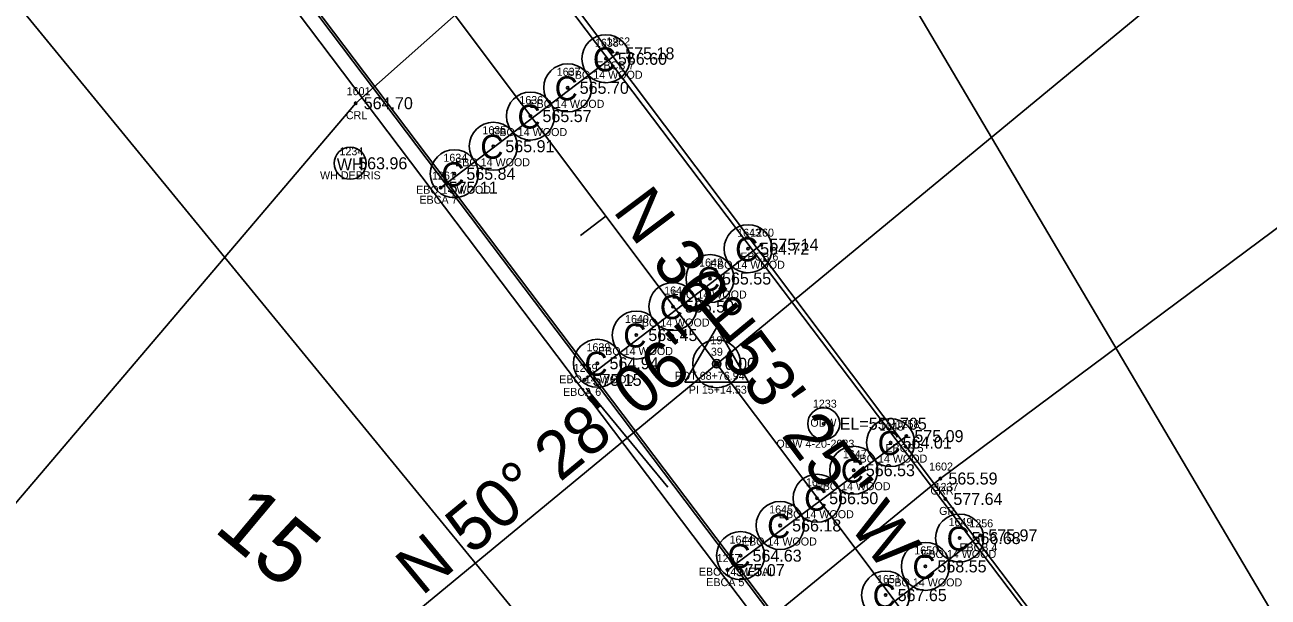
# Model space of a CAD drawing. Extents: x 1694813 to 1696862, y 1086485 to 1091027.
# Drawn here: x 1695795.8 to 1695951.1, y 1089028.7 to 1089100.2 of the extents above; entities that cross this region are included whole.
import ezdxf

# ---------------------------------------------------------------- set-up
doc = ezdxf.new("R2010")
doc.units = 0
for name, color, linetype in [('RD_EX_Bridge', 7, 'Continuous'), ('RD_EX_Bridge_txCode', 7, 'Continuous'), ('RD_EX_GuardRail', 7, 'Continuous'), ('RD_EX_GuardRail_txCode', 7, 'Continuous'), ('RD_EX_H2O', 7, 'Continuous'), ('RD_EX_H2O_txCode', 7, 'Continuous'), ('RD_EX_Misc', 7, 'Continuous'), ('RD_EX_TX_Bridge_ELEV', 7, 'Continuous'), ('RD_EX_TX_GuardRail_ELEV', 7, 'Continuous'), ('RD_EX_TX_H2O_ELEV', 7, 'Continuous'), ('RD_EX_VEG', 7, 'Continuous'), ('RD_HC_Cl', 7, 'Continuous'), ('RD_HC_Data', 7, 'Continuous'), ('RD_HC_Data_Tic', 7, 'Continuous'), ('RD_HC_Survey_ELEV', 7, 'Continuous'), ('RD_HC_TX_Sta50', 7, 'Continuous'), ('RD_HC_txCode', 7, 'Continuous'), ('RD_SMD_Locator', 7, 'Continuous')]:
    doc.layers.add(name, color=color, linetype=linetype)

msp = doc.modelspace()

# ---------------------------------------------------------------- linework, layer by layer
at = {"layer": 'RD_EX_Bridge'}
for p, q in [((1695847.7, 1089079.83), (1695869.76, 1089096.61)), ((1695865.67, 1089055.82), (1695887.77, 1089072.72)), ((1695883.54, 1089032.04), (1695905.88, 1089048.79)), ((1695893.25, 1089019.58), (1695915.11, 1089036.39))]:
    msp.add_line(p, q, dxfattribs=at)
msp.add_lwpolyline([(1695941.01, 1089000.23), (1695920.78, 1088984.87), (1695803.35, 1089140.32), (1695823.67, 1089155.36), (1695941.01, 1089000.23)], dxfattribs=at)
for centre in [(1695868.34, 1089095.94), (1695863.57, 1089092.31), (1695858.92, 1089088.78), (1695854.28, 1089085.01), (1695849.41, 1089081.57), (1695886.11, 1089072.2), (1695881.35, 1089068.48), (1695876.71, 1089064.98), (1695872.14, 1089061.42), (1695867.29, 1089057.89), (1695903.91, 1089047.98), (1695899.31, 1089044.53), (1695894.73, 1089041.03), (1695890.11, 1089037.62), (1695912.52, 1089036.05), (1695885.16, 1089033.85), (1695908.26, 1089032.51), (1695903.29, 1089028.92)]:
    msp.add_circle(centre, 3, dxfattribs=at)
at = {"layer": 'RD_EX_GuardRail'}
for points in [[(1695954.25, 1088939.4), (1695922.07, 1088982.8), (1695888.95, 1089026.55), (1695824.62, 1089111.72), (1695774.33, 1089183.16), (1695747.02, 1089230.32), (1695728.79, 1089274.77), (1695712.04, 1089332.59)], [(1695975.12, 1088955.36), (1695942.2, 1088999.47), (1695910.75, 1089040.94), (1695844.49, 1089129.18), (1695795.31, 1089197.37)]]:
    msp.add_lwpolyline(points, dxfattribs=at)
at = {"layer": 'RD_EX_H2O'}
for points in [[(1695741.44, 1088979.77), (1695766.31, 1089008.66), (1695772.21, 1089014.13), (1695837.09, 1089090.39), (1695860.76, 1089111.44), (1695929.31, 1089152.28), (1696035.3, 1089183.03), (1696164.17, 1089149.21), (1696221.7, 1089111.38), (1696248.95, 1089080.06), (1696273.19, 1089047.83), (1696283.59, 1089011.28), (1696295.68, 1088944.39)], [(1695520.92, 1088704.05), (1695627.53, 1088770.84), (1695697.51, 1088817.15), (1695757.08, 1088884.85), (1695828.4, 1088961.5), (1695887.69, 1089025.09), (1695910.13, 1089043.49), (1695963.83, 1089083.42), (1696041.69, 1089105.91), (1696137.07, 1089082.48), (1696174.24, 1089034.61), (1696185.76, 1089011.54), (1696200.45, 1088973.14), (1696214.06, 1088899.28)]]:
    msp.add_lwpolyline(points, dxfattribs=at)
for centre, radius in [((1695836.4, 1089082.88), 2), ((1695836.4, 1089082.88), 0.005), ((1695895.55, 1089050.34), 2), ((1695895.55, 1089050.34), 0.15)]:
    msp.add_circle(centre, radius, dxfattribs=at)
at = {"layer": 'RD_EX_Misc'}
msp.add_line((1695918.59, 1088984.27), (1695801.38, 1089139.4), dxfattribs=at)
at = {"layer": 'RD_EX_VEG'}
for points in [[(1695767.04, 1087738.17), (1695850.84, 1087719.29), (1695876.92, 1087874.52), (1695886.77, 1087978.73), (1695882.04, 1088123.19), (1695966.35, 1088397.22), (1695987.61, 1088500.99), (1696016.82, 1088604.01), (1696023.94, 1088658.84), (1696026.75, 1088706.17), (1696020.44, 1088756.26), (1696012.04, 1088803.02), (1695995.69, 1088847.32), (1695967.16, 1088892.48), (1695790.95, 1089107.47), (1695767.01, 1089177.35), (1695741.24, 1089223.37), (1695720.39, 1089271.33), (1695703.52, 1089329.03), (1695695, 1089381.13)], [(1695933.86, 1087837.25), (1695947.67, 1087971.41), (1695951.18, 1088015.29), (1695955.07, 1088071.66), (1695974.95, 1088229.99), (1695984.06, 1088281.51), (1695991.57, 1088334), (1696002.15, 1088386.49), (1696032.05, 1088491.59), (1696059.12, 1088595.39), (1696074.06, 1088653.09), (1696077.62, 1088703.57), (1696070.4, 1088760.42), (1696059.88, 1088817.29), (1696044.37, 1088867.3), (1696013.5, 1088916.36), (1695990.24, 1088961.27), (1695859.14, 1089183.28), (1695912, 1089200.8)]]:
    msp.add_lwpolyline(points, dxfattribs=at)
at = {"layer": 'RD_HC_Cl'}
for p, q in [((1695971.3, 1088939.1), (1695801.51, 1089165.33)), ((1695799.79, 1088989.83), (1695937.83, 1089103.75))]:
    msp.add_line(p, q, dxfattribs=at)
at = {"layer": 'RD_HC_Data'}
for p, q in [((1695878.22, 1089055.54), (1695882.19, 1089062.42)), ((1695882.19, 1089062.42), (1695886.16, 1089055.54)), ((1695878.22, 1089055.54), (1695886.16, 1089055.54))]:
    msp.add_line(p, q, dxfattribs=at)
for radius in [3, 0.529, 0.282]:
    msp.add_circle((1695882.19, 1089057.83), radius, dxfattribs=at)
at = {"layer": 'RD_HC_Data_Tic'}
for p, q in [((1695868.35, 1089076.27), (1695865.15, 1089073.87)), ((1695870.99, 1089048.59), (1695865.89, 1089054.76)), ((1695870.99, 1089048.59), (1695876.08, 1089042.42))]:
    msp.add_line(p, q, dxfattribs=at)
at = {"layer": 'RD_SMD_Locator'}
for centre in [(1695869.76, 1089096.61), (1695868.34, 1089095.94), (1695863.57, 1089092.31), (1695837.09, 1089090.39), (1695858.92, 1089088.78), (1695854.28, 1089085.01), (1695849.41, 1089081.57), (1695847.7, 1089079.83), (1695886.11, 1089072.2), (1695887.77, 1089072.72), (1695881.35, 1089068.48), (1695876.71, 1089064.98), (1695872.14, 1089061.42), (1695867.29, 1089057.89), (1695882.19, 1089057.83), (1695882.19, 1089057.83), (1695865.67, 1089055.82), (1695905.88, 1089048.79), (1695903.91, 1089047.98), (1695899.31, 1089044.53), (1695910.13, 1089043.49), (1695894.73, 1089041.03), (1695910.75, 1089040.94), (1695890.11, 1089037.62), (1695912.52, 1089036.05), (1695915.11, 1089036.39), (1695885.16, 1089033.85), (1695908.26, 1089032.51), (1695883.54, 1089032.04), (1695903.29, 1089028.92)]:
    msp.add_circle(centre, 0.15, dxfattribs=at)

# ---------------------------------------------------------------- texts
at = {"layer": 'RD_EX_Bridge'}
for p in [(1695866.71, 1089094.37), (1695861.94, 1089090.75), (1695857.29, 1089087.22), (1695852.65, 1089083.45), (1695847.78, 1089080), (1695884.48, 1089070.63), (1695879.72, 1089066.92), (1695875.07, 1089063.41), (1695870.51, 1089059.86), (1695865.66, 1089056.33), (1695902.28, 1089046.42), (1695897.68, 1089042.97), (1695893.1, 1089039.47), (1695888.48, 1089036.06), (1695910.89, 1089034.49), (1695883.53, 1089032.29), (1695906.63, 1089030.95), (1695901.66, 1089027.36)]:
    msp.add_text('C', height=3, dxfattribs=at).set_placement(p)
at = {"layer": 'RD_EX_Bridge_txCode'}
for s, p in [('1638', (1695866.97, 1089097.44)), ('1262', (1695868.39, 1089097.61)), ('1637', (1695862.2, 1089093.81)), ('EBCB 7', (1695867.14, 1089094.61)), ('EBO 14 WOOD', (1695863.56, 1089093.44)), ('1636', (1695857.53, 1089090.28)), ('EBO 14 WOOD', (1695858.79, 1089089.81)), ('1635', (1695852.91, 1089086.51)), ('EBO 14 WOOD', (1695854.14, 1089086.28)), ('1634', (1695848.04, 1089083.07)), ('EBO 14 WOOD', (1695849.5, 1089082.51)), ('1261', (1695846.61, 1089080.83)), ('EBO 14 WOOD', (1695844.63, 1089079.07)), ('EBCA 7', (1695845.05, 1089077.83)), ('1643', (1695884.74, 1089073.7)), ('1260', (1695886.36, 1089073.72)), ('EBCB 6', (1695885.13, 1089070.72)), ('1642', (1695879.98, 1089069.98)), ('EBO 14 WOOD', (1695881.33, 1089069.7)), ('1641', (1695875.62, 1089066.48)), ('EBO 14 WOOD', (1695876.57, 1089065.98)), ('1640', (1695870.73, 1089062.92)), ('EBO 14 WOOD', (1695871.93, 1089062.48)), ('1639', (1695865.92, 1089059.39)), ('EBO 14 WOOD', (1695867.36, 1089058.92)), ('1259', (1695864.32, 1089056.82)), ('EBO 14 WOOD', (1695862.51, 1089055.39)), ('EBCA 6', (1695862.99, 1089053.82)), ('1648', (1695902.54, 1089049.48)), ('1258', (1695904.53, 1089049.79)), ('1647', (1695897.94, 1089046.03)), ('EBCB 5', (1695903.26, 1089046.79)), ('EBO 14 WOOD', (1695899.13, 1089045.48)), ('1646', (1695893.33, 1089042.53)), ('EBO 14 WOOD', (1695894.53, 1089042.03)), ('1645', (1695888.74, 1089039.12)), ('EBO 14 WOOD', (1695889.95, 1089038.53)), ('1649', (1695911.15, 1089037.55)), ('1256', (1695913.74, 1089037.39)), ('1644', (1695883.79, 1089035.35)), ('EBO 14 WOOD', (1695885.33, 1089035.12)), ('1650', (1695906.86, 1089034.01)), ('EBO 14 WOOD', (1695907.74, 1089033.55)), ('EBCB 4', (1695912.49, 1089034.39)), ('1257', (1695882.19, 1089033.04)), ('EBO 14 METAL', (1695879.95, 1089031.35)), ('1651', (1695902.21, 1089030.42)), ('EBCA 5', (1695880.88, 1089030.04)), ('EBO 14 WOOD', (1695903.49, 1089030.01))]:
    msp.add_text(s, height=1, dxfattribs=at).set_placement(p)
at = {"layer": 'RD_EX_GuardRail_txCode'}
for s, p in [('1237', (1695909.4, 1089041.94)), ('GR', (1695909.97, 1089038.94))]:
    msp.add_text(s, height=1, dxfattribs=at).set_placement(p)
at = {"layer": 'RD_EX_H2O'}
for s, height, p in [('WH', 1.5, (1695834.73, 1089082)), ('ODW', 1, (1695893.88, 1089049.96))]:
    msp.add_text(s, height=height, dxfattribs=at).set_placement(p)
at = {"layer": 'RD_EX_H2O_txCode'}
for s, p in [('1601', (1695835.96, 1089091.39)), ('CRL', (1695835.86, 1089088.39)), ('1234', (1695835.06, 1089083.88)), ('WH DEBRIS', (1695832.63, 1089080.88)), ('1233', (1695894.2, 1089052.34)), ('ODW 4-20-2023', (1695889.64, 1089047.34)), ('1602', (1695908.72, 1089044.49)), ('CRR', (1695908.88, 1089041.49))]:
    msp.add_text(s, height=1, dxfattribs=at).set_placement(p)
at = {"layer": 'RD_EX_TX_Bridge_ELEV'}
for s, p in [('566.60', (1695869.84, 1089095.19)), ('575.18', (1695870.76, 1089095.86)), ('565.70', (1695865.07, 1089091.56)), ('565.57', (1695860.42, 1089088.03)), ('565.91', (1695855.78, 1089084.26)), ('565.84', (1695850.91, 1089080.82)), ('575.11', (1695848.7, 1089079.08)), ('575.14', (1695888.77, 1089071.97)), ('564.72', (1695887.61, 1089071.45)), ('565.55', (1695882.85, 1089067.73)), ('565.50', (1695878.21, 1089064.23)), ('565.45', (1695873.64, 1089060.67)), ('564.94', (1695868.79, 1089057.14)), ('575.15', (1695866.67, 1089055.07)), ('564.01', (1695905.41, 1089047.23)), ('575.09', (1695906.88, 1089048.04)), ('566.53', (1695900.81, 1089043.78)), ('566.50', (1695896.23, 1089040.28)), ('566.18', (1695891.61, 1089036.87)), ('566.68', (1695914.02, 1089035.3)), ('575.97', (1695916.11, 1089035.64)), ('564.63', (1695886.66, 1089033.1)), ('575.07', (1695884.54, 1089031.29)), ('568.55', (1695909.76, 1089031.76)), ('567.65', (1695904.79, 1089028.17))]:
    msp.add_text(s, height=1.5, dxfattribs=at).set_placement(p)
at = {"layer": 'RD_EX_TX_GuardRail_ELEV'}
msp.add_text('577.64', height=1.5, dxfattribs=at).set_placement((1695911.75, 1089040.19))
at = {"layer": 'RD_EX_TX_H2O_ELEV'}
for s, p in [('564.70', (1695838.09, 1089089.64)), ('563.96', (1695837.4, 1089082.13)), ('EL=559.705', (1695897.55, 1089049.59)), ('565.59', (1695911.13, 1089042.74))]:
    msp.add_text(s, height=1.5, dxfattribs=at).set_placement(p)
at = {"layer": 'RD_HC_Data'}
for s, rotation, p in [('N 36%%d 53\' 25" W', 306.8901, (1695869.1, 1089076.94)), ('N 50%%d 28\' 06" E', 39.5316, (1695845.34, 1089028.72))]:
    msp.add_text(s, height=6, rotation=rotation, dxfattribs=at).set_placement(p)
at = {"layer": 'RD_HC_Survey_ELEV'}
msp.add_text('0.00', height=1.5, dxfattribs=at).set_placement((1695883.19, 1089057.08))
msp.add_text('0.00', height=1.5, dxfattribs=at).set_placement((1695883.19, 1089057.08))
at = {"layer": 'RD_HC_TX_Sta50'}
msp.add_text('15', height=8, rotation=320.0994, dxfattribs=at).set_placement((1695819.19, 1089037.04))
at = {"layer": 'RD_HC_txCode'}
for s, p in [('19', (1695881.41, 1089060.26)), ('39', (1695881.46, 1089058.83)), ('POT 68+76.94', (1695876.94, 1089055.83)), ('PI 15+14.53', (1695878.69, 1089054.09))]:
    msp.add_text(s, height=1, dxfattribs=at).set_placement(p)

doc.saveas('drawing.dxf')
